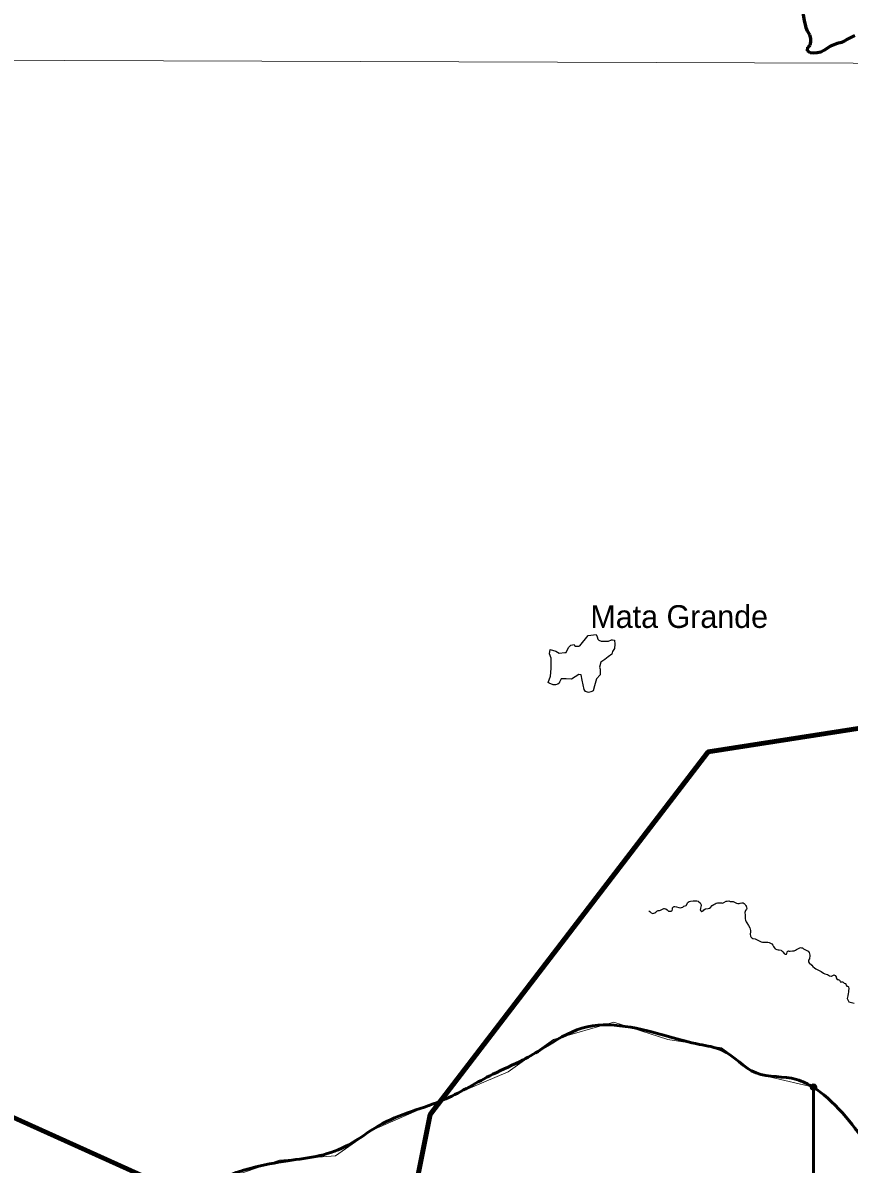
# Model space of a CAD drawing. Extents: x -1643653 to 4543381, y 1624270 to 13878484.
# Drawn here: x 627167 to 645322, y 8980683 to 9005760 of the extents above; entities that cross this region are included whole.
import ezdxf

# ---------------------------------------------------------------- set-up
doc = ezdxf.new("R2010")
doc.units = 0
doc.header["$LTSCALE"] = 200
doc.header["$PDMODE"] = 32
doc.header["$PDSIZE"] = 100
doc.linetypes.add('LONG_DASH_SHORT_DASH', pattern=[9.9, 6, -1.2, 1.5, -1.2])
for name, color, linetype, lineweight in [('1', 7, 'Continuous', 13), ('21', 7, 'Continuous', 25), ('24', 7, 'Continuous', 25), ('58', 7, 'Continuous', 13), ('59', 7, 'Continuous', 53), ('60', 7, 'Continuous', 13), ('7', 7, 'LONG_DASH_SHORT_DASH', 60), ('9', 7, 'Continuous', 90)]:
    doc.layers.add(name, color=color, linetype=linetype, lineweight=lineweight)
doc.layers.add('41', color=7, linetype='Continuous')

msp = doc.modelspace()

# ---------------------------------------------------------------- linework, layer by layer
at = {"layer": '1'}
msp.add_lwpolyline([(565303.2, 9005146.6), (664889.8, 9004806.7), (719872.1, 9004543.9), (790635.8, 9004109)], dxfattribs=at)
at = {"layer": '21'}
msp.add_lwpolyline([(639985.7, 8992170.7), (640033.2, 8992177.5), (640101, 8992204.6), (640121.3, 8992204.6), (640168.8, 8992197.9), (640175.6, 8992109.7), (640168.8, 8992014.7), (640121.3, 8991946.8), (640107.8, 8991885.7), (640026.4, 8991831.5), (639951.8, 8991770.4), (639863.6, 8991716.1), (639836.5, 8991600.8), (639850, 8991560.1), (639850, 8991431.1), (639768.6, 8991349.7), (639727.9, 8991193.7), (639700.8, 8991085.1), (639666.9, 8991064.8), (639646.5, 8991058), (639592.3, 8991044.4), (639531.2, 8991064.8), (639497.3, 8991112.2), (639456.6, 8991315.8), (639436.3, 8991431.1), (639382, 8991444.7), (639300.6, 8991390.4), (639219.2, 8991336.2), (639103.9, 8991342.9), (638995.4, 8991342.9), (638954.7, 8991275.1), (638947.9, 8991248), (638920.8, 8991227.6), (638873.3, 8991214), (638819, 8991214), (638730.8, 8991254.7), (638710.5, 8991268.3), (638758, 8991404), (638778.3, 8991573.6), (638771.6, 8991797.5), (638737.6, 8991899.3), (638751.2, 8991987.5), (638880.1, 8991953.6), (638947.9, 8991912.9), (639076.8, 8991926.5), (639103.9, 8991926.5), (639158.2, 8992035), (639205.7, 8992089.3), (639280.3, 8992102.9), (639287, 8992075.7), (639307.4, 8992062.2), (639327.7, 8992062.2), (639348.1, 8992062.2), (639382, 8992062.2), (639402.3, 8992068.9), (639585.5, 8992299.6), (639761.8, 8992320), (639782.2, 8992272.5), (639802.5, 8992218.2), (639822.9, 8992197.9), (639870.4, 8992177.5)], close=True, dxfattribs=at)
at = {"layer": '24'}
for points in [[(640918.4, 8986246.1), (640939.3, 8986233.2), (640958.6, 8986220.4), (640974.7, 8986202.7), (641005.2, 8986193), (641027.8, 8986197.9), (641050.3, 8986207.5), (641076.6, 8986220.6), (641099, 8986243.2), (641125.1, 8986253.3), (641153.7, 8986258.2), (641180.7, 8986267.4), (641247.9, 8986299.8), (641252.4, 8986300.8), (641265.9, 8986300.5), (641292.7, 8986293.1), (641322, 8986270.3), (641342.1, 8986250.7), (641354.3, 8986244.5), (641374.6, 8986241.8), (641397.6, 8986241), (641413.7, 8986242.2), (641425.8, 8986248.1), (641430.8, 8986256.1), (641439.1, 8986285), (641439.6, 8986307.4), (641442.2, 8986313.7), (641465.6, 8986337.5), (641476.7, 8986343.9), (641494.1, 8986344.5), (641529.5, 8986336.6), (641579.3, 8986318.8), (641613.9, 8986317), (641641.7, 8986320.3), (641665.2, 8986332.1), (641689, 8986354.9), (641716.6, 8986356.6), (641739.9, 8986363.2), (641749.1, 8986376.7), (641769.3, 8986422.7), (641783.8, 8986436.1), (641809.2, 8986452.8), (641838.7, 8986459.2), (641897.4, 8986468), (641950.8, 8986470.9), (641977.8, 8986468.7), (642001.6, 8986462.8), (642022.7, 8986446.3), (642045.1, 8986422.7), (642062.2, 8986395.1), (642067.7, 8986379.8), (642067.4, 8986365.3), (642059.7, 8986311), (642053.8, 8986298.9), (642051, 8986272.1), (642060.4, 8986246.1), (642074.6, 8986231), (642083.8, 8986229.3), (642088.7, 8986230.9), (642112.8, 8986245.9), (642131.7, 8986271.2), (642167.5, 8986292.7), (642223.9, 8986298.8), (642254.2, 8986307.8), (642273.7, 8986320.8), (642314.6, 8986365.6), (642348.1, 8986390.6), (642375.5, 8986406.4), (642402.4, 8986416.7), (642429.4, 8986421.7), (642455.4, 8986424.7), (642486, 8986422.9), (642515, 8986422.7), (642542.8, 8986419), (642568.2, 8986430.8), (642620.2, 8986459.8), (642643.2, 8986464.7), (642676.8, 8986465.5), (642708.6, 8986455), (642772.3, 8986450.6), (642818.2, 8986429.7), (642843.8, 8986419.7), (642873.8, 8986412.4), (642902.4, 8986413.3), (642931.2, 8986419.8), (642961.1, 8986424.8), (642990.2, 8986421.6), (643016.2, 8986411.7), (643039.1, 8986389.9), (643046.4, 8986376.2), (643052.1, 8986372.3), (643069.2, 8986330.8), (643073.5, 8986303.9), (643070.2, 8986285), (643047.5, 8986257.6), (643036.1, 8986236.1), (643032.3, 8986209.7), (643037.2, 8986151.9), (643037.4, 8986120.1), (643040.2, 8986072.2), (643045.5, 8986041.5)], [(643045.5, 8986041.5), (643045.5, 8986041.5), (643056, 8986011.1), (643071.6, 8985984.1), (643109.4, 8985927.6), (643137, 8985874.4), (643147.9, 8985846.7), (643153.9, 8985815.2), (643153.8, 8985788.4), (643147.7, 8985733.6), (643151.8, 8985695.4), (643163.7, 8985678), (643182.5, 8985656.3), (643204.1, 8985642.6), (643255.2, 8985632.2), (643391.8, 8985570.3), (643419.6, 8985560.6), (643448.3, 8985559.2), (643535.1, 8985564.4), (643566.8, 8985554.4), (643593.8, 8985539.8), (643620, 8985522.8), (643645.8, 8985498.4), (643661.8, 8985469), (643671.2, 8985440.6), (643696.1, 8985416.2), (643730.8, 8985396.7), (643760.5, 8985389.3), (643787.3, 8985391.9), (643824.7, 8985383.8), (643827.6, 8985378.5), (643844.2, 8985367.4), (643865.5, 8985345.4), (643891.9, 8985312.7), (643902.2, 8985304.6), (643918.1, 8985298.3), (643931.2, 8985298.1), (643942, 8985300.2), (643956, 8985315.2), (643958.1, 8985343.4), (643962.6, 8985351.1), (643974.6, 8985365.4), (643986.6, 8985368.4), (643998.1, 8985366.4), (644024.1, 8985364.5), (644080, 8985371.7), (644110.9, 8985373), (644143.4, 8985382.5), (644168.5, 8985396.6), (644196.1, 8985417.2), (644224.2, 8985431.8), (644254, 8985444.8), (644273.9, 8985433.2), (644296.8, 8985435.6), (644322.2, 8985414.2), (644363.5, 8985395.3), (644391.1, 8985376.3), (644419.5, 8985362.5), (644442.3, 8985331.1), (644453.3, 8985302.5), (644457.5, 8985272.5), (644457.4, 8985247.7), (644454.2, 8985219.9), (644448.7, 8985192.2), (644431.3, 8985165), (644427.1, 8985155.8), (644427.3, 8985131.1), (644442.3, 8985109.9), (644498.8, 8985056.6), (644525.5, 8985029), (644563, 8984997.2), (644593.4, 8984976), (644619.6, 8984960.8), (644704.7, 8984916.9), (644762.1, 8984880.9), (644788.2, 8984867.8), (644814.3, 8984857.8), (644846.8, 8984850.4), (644871.5, 8984838.7), (644888.1, 8984823.5), (644924.3, 8984813.9), (644936.7, 8984813.3), (644980.1, 8984838.3), (644995.5, 8984839.8), (644999.2, 8984838.9), (645011.4, 8984829.6), (645036.6, 8984800.8), (645040, 8984774.7), (645055.3, 8984741.8), (645079.3, 8984738.2), (645111, 8984727.2), (645116.6, 8984716.9), (645122.7, 8984692.8), (645125.9, 8984690.1), (645134.7, 8984687.1), (645179, 8984687.9), (645191.9, 8984684.7), (645204.7, 8984665), (645215.6, 8984660.4), (645240.1, 8984653.1), (645246.2, 8984645.1)], [(645246.2, 8984645.1), (645252, 8984633.7), (645252, 8984633.7), (645252.8, 8984617.9), (645254.9, 8984614.1), (645273, 8984596.3), (645297.8, 8984587.5), (645307.1, 8984577.2), (645309.6, 8984572.6), (645313.5, 8984545.7), (645310.3, 8984489.1), (645306.1, 8984462.2), (645298.7, 8984433.5), (645293.2, 8984378.7), (645284.9, 8984350.8), (645279.8, 8984323.9), (645312.4, 8984251.8), (645435.1, 8984220.4)]]:
    msp.add_lwpolyline(points, dxfattribs=at)
at = {"layer": '58'}
for points in [[(645448.7, 9005484.8), (645288.2, 9005403.7), (645230.5, 9005363.3), (645150.3, 9005327.8), (645057.4, 9005307.2), (644911.9, 9005243.8), (644769.1, 9005152.8), (644701.4, 9005117.3), (644621.1, 9005096.9), (644548.2, 9005094), (644465.3, 9005103.7), (644409.8, 9005143.6), (644412.1, 9005221.5), (644464.7, 9005269.4), (644479.5, 9005342.3), (644479.2, 9005417.6), (644458.8, 9005497.9), (644408.2, 9005575.5), (644377.8, 9005648.2), (644360, 9005720.9), (644342.1, 9005803.7), (644318.9, 9005944.2), (644281, 9006014.3), (644220.5, 9006056.8)], [(628372, 8978627.3), (629294.9, 8978920), (630669.6, 8979678.9), (631001.5, 8979963.5), (631570.3, 8980342.9), (632802.9, 8980769.8), (634035.4, 8980864.7), (634841.3, 8981433.8), (635931.7, 8981908.1), (637827.9, 8982714.4), (638823.4, 8983425.8), (640150.8, 8983805.3), (641335.9, 8983425.8), (642521, 8983236.1), (643279.5, 8982667), (644540.6, 8982372.7), (644540.6, 8982372.7)]]:
    msp.add_lwpolyline(points, dxfattribs=at)
msp.add_spline([(644540.6, 8982372.7), (644675.9, 8982274.9), (645321.7, 8981636.4), (645853, 8981011.1), (646805.1, 8980473.1), (647606.1, 8980240.8), (648482.7, 8979868.5), (649626.6, 8979469.5), (650871.6, 8978943), (651404, 8978495.7), (652521.8, 8977995.2), (653308.2, 8977445.1), (653712.6, 8976883.9), (654308.9, 8976487.2), (655070.4, 8976039), (655983.7, 8975399.4)], degree=3, dxfattribs=at)
at = {"layer": '59'}
msp.add_line((644540.6, 8982372.7), (644540.6, 8982372.7), dxfattribs=at)
for points in [[(644540.6, 8982372.7), (644540.6, 8970393.7), (643561.6, 8971154.3), (643526.5, 8971171.9), (642848, 8971358.9), (642760.5, 8971341.8), (641184, 8970130.5)], [(643561.6, 8971154.3), (644540.6, 8970393.7), (644540.6, 8982372.7)]]:
    msp.add_lwpolyline(points, dxfattribs=at)
for points in [[(644540.6, 8982372.7), (644168, 8982544), (643277.3, 8982687.6), (642528.8, 8983186.6), (642032.9, 8983315.8), (641371.6, 8983483.9), (639449.6, 8983669.8), (638593.8, 8983228.2), (638159.4, 8982975.7), (637495.4, 8982660.5), (636460.7, 8982117.9), (634980.1, 8981526.3), (634328.2, 8981109.3), (633690, 8980870.4), (632989, 8980758.8), (632185.7, 8980596.8), (631534.8, 8980357.8), (631164.1, 8980105), (630703.5, 8979738.1), (630051.8, 8979346.6), (629272.1, 8978853.8), (628372, 8978627.3)], [(655983.7, 8975399.4), (655070.4, 8976039), (654308.9, 8976487.2), (653712.6, 8976883.9), (653308.2, 8977445.1), (652521.8, 8977995.2), (651404, 8978495.7), (650871.6, 8978943), (649626.6, 8979469.5), (648482.7, 8979868.5), (647606.1, 8980240.8), (646805.1, 8980473.1), (645853, 8981011.1), (645321.7, 8981636.4), (644675.9, 8982274.9), (644540.6, 8982372.7)]]:
    msp.add_spline(points, degree=3, dxfattribs=at)
msp.add_point((644540.6, 8982372.7), dxfattribs=at)
at = {"layer": '60', "lineweight": 25}
msp.add_spline([(814781, 9009175.5), (814787.2, 9009173.4), (814796.9, 9009173.4), (814799.4, 9009172.4), (814805.1, 9009174.5), (814805.6, 9009176.5), (814811.7, 9009179.5), (814811.7, 9009179.5), (814801.5, 9009181), (814790.7, 9009181.5), (814784.1, 9009183.1), (814777.4, 9009185.1), (814778.4, 9009175.5)], degree=3, dxfattribs=at)
at = {"layer": '7'}
msp.add_lwpolyline([(645448.7, 9005484.8), (645288.2, 9005403.7), (645230.5, 9005363.3), (645150.3, 9005327.8), (645057.4, 9005307.2), (644911.9, 9005243.8), (644769.1, 9005152.8), (644701.4, 9005117.3), (644621.1, 9005096.9), (644548.2, 9005094), (644465.3, 9005103.7), (644409.8, 9005143.6), (644412.1, 9005221.5), (644464.7, 9005269.4), (644479.5, 9005342.3), (644479.2, 9005417.6), (644458.8, 9005497.9), (644408.2, 9005575.5), (644377.8, 9005648.2), (644360, 9005720.9), (644342.1, 9005803.7), (644318.9, 9005944.2), (644281, 9006014.3), (644220.5, 9006056.8)], dxfattribs=at)
at = {"layer": '9'}
for points in [[(635350.7, 8977923.9), (636116.8, 8981777.4), (642228, 8989744.8), (647160.3, 8990514), (649828, 8995545.6), (655722.5, 9001435.5), (661506.7, 9009120.3)], [(637260.6, 8972975.8), (637390.8, 8977204.2), (635350.7, 8977923.9), (623791.9, 8983133)]]:
    msp.add_lwpolyline(points, dxfattribs=at)

# ---------------------------------------------------------------- texts
at = {"layer": '41'}
msp.add_text('Mata Grande', height=500, dxfattribs=at).set_placement((639637.3, 8992464.7))

doc.saveas('drawing.dxf')
